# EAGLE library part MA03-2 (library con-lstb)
PIN HEADER
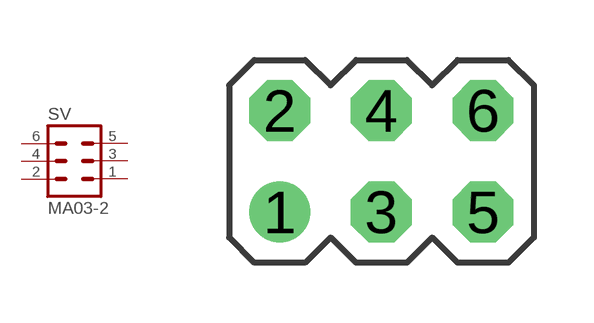
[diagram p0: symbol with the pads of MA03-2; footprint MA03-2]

Designator prefix SV

## MA03-2 (OC_FARNELL: unknown; OC_NEWARK: unknown)  [MA03-2]
1  1  pas
2  2  pas
3  3  pas
4  4  pas
5  5  pas
6  6  pas

## Footprint MA03-2 (pad centres in mm)
PIN HEADER
drill 1.016 round: 1 -2.54,-1.27
drill 1.016 octagon: 2 -2.54,1.27; 3 0,-1.27; 4 0,1.27; 5 2.54,-1.27; 6 2.54,1.27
